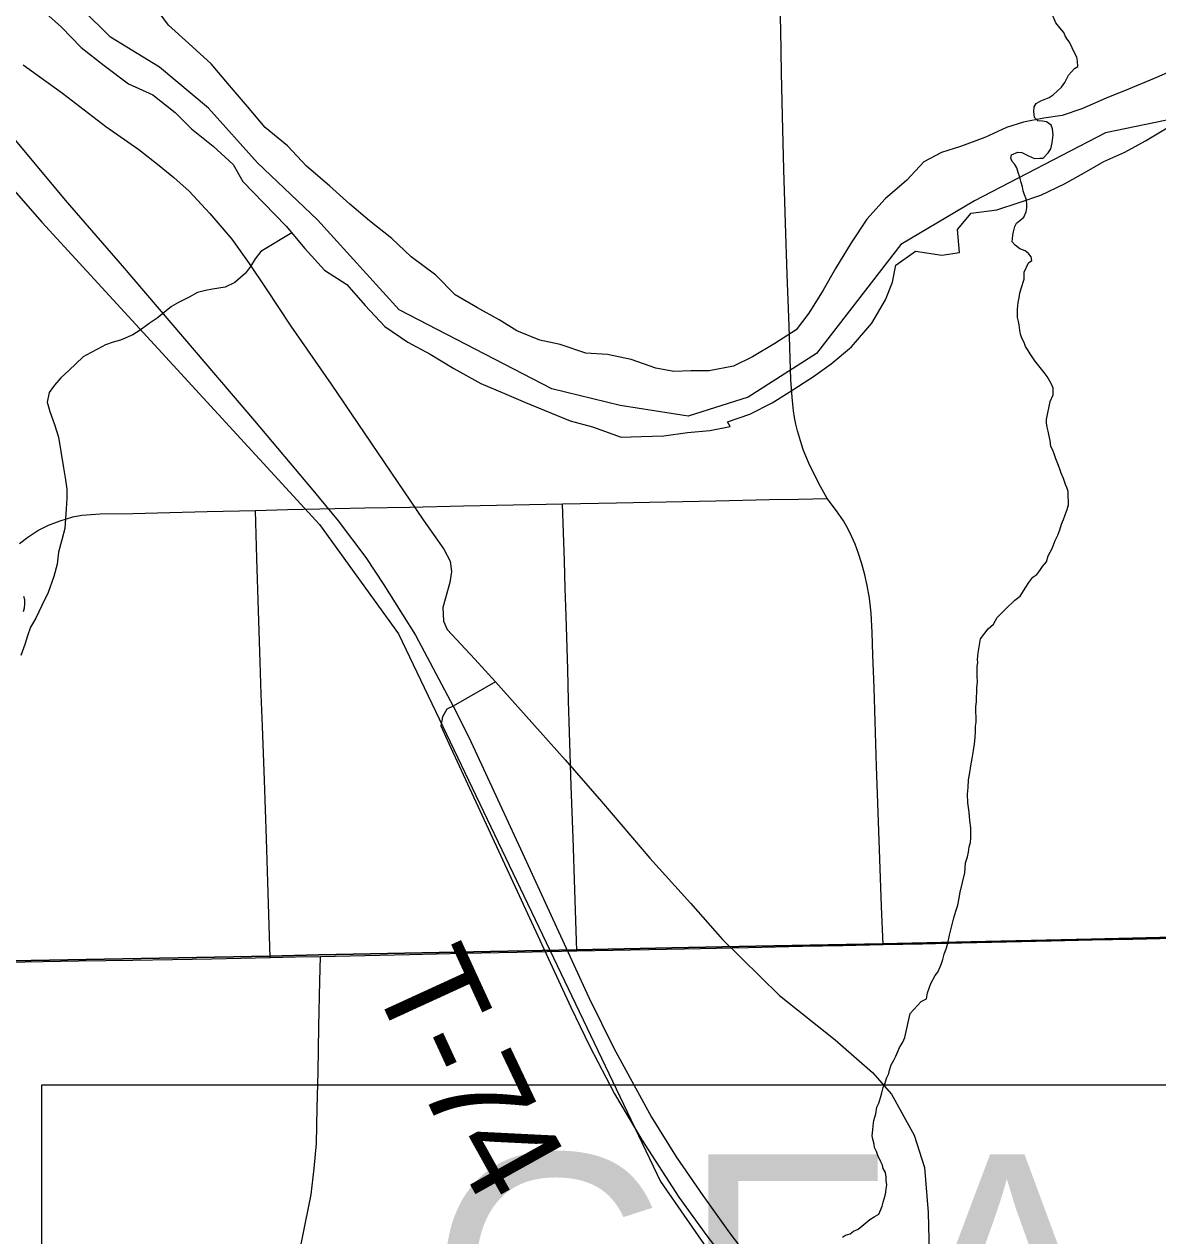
# Model space of a CAD drawing. Extents: x -6.1 to 38, y -7.7 to 22.
# Drawn here: x 3.606 to 4.259, y 19.227 to 19.926 of the extents above; entities that cross this region are included whole.
import ezdxf

# ---------------------------------------------------------------- set-up
doc = ezdxf.new("R2010")
doc.units = 0
for name, color, linetype in [('GM_X_Corporation', 7, 'Continuous'), ('GM_X_County_Road', 7, 'Continuous'), ('GM_X_Major_River', 7, 'Continuous'), ('GM_X_Minor_River', 7, 'Continuous'), ('GM_X_Rail_Line', 7, 'Continuous'), ('GM_X_Township_Road', 7, 'Continuous'), ('GM_X_Township_Road_Text', 7, 'Continuous'), ('GM_X_US_Route', 7, 'Continuous'), ('SH_Text', 7, 'Continuous')]:
    doc.layers.add(name, color=color, linetype=linetype)

msp = doc.modelspace()

# ---------------------------------------------------------------- linework, layer by layer
at = {"layer": 'GM_X_Corporation'}
for points in [[(6.96628, 20.9), (2.1, 20.9), (2.1, 19.36551), (3.07052, 19.37611), (3.09907, 19.37662), (3.10966, 19.37681), (3.12026, 19.377), (3.14426, 19.37751), (3.74766, 19.38857), (3.77587, 19.3894), (3.92442, 19.39221), (3.97926, 19.39329), (4.02764, 19.39424), (4.10065, 19.39567), (4.15155, 19.39684), (4.22089, 19.39843), (4.27649, 19.3997)], [(4.32021, 19.88191), (4.2291, 19.86308), (4.15368, 19.82382), (4.11127, 19.79868), (4.06254, 19.73585), (4.02327, 19.71072), (3.98871, 19.69973), (3.94944, 19.70602), (3.91017, 19.71546), (3.82222, 19.76103), (3.77511, 19.81289), (3.74056, 19.84589), (3.7123, 19.87731), (3.68403, 19.90089), (3.65576, 19.91817), (3.62279, 19.95117), (3.59767, 19.97946), (3.59394, 19.99773), (3.57833, 20.03194), (3.57893, 20.04876), (3.51164, 20.05197), (3.36656, 20.05475), (3.29133, 20.05869), (2.61918, 20.0796)], [(4.32021, 19.88191), (4.2291, 19.86308), (4.15368, 19.82382), (4.11127, 19.79868), (4.06254, 19.73585), (4.02327, 19.71072), (3.98871, 19.69973), (3.94944, 19.70602), (3.91017, 19.71546), (3.82222, 19.76103), (3.77511, 19.81289), (3.74056, 19.84589), (3.7123, 19.87731), (3.68403, 19.90089), (3.65576, 19.91817), (3.62279, 19.95117), (3.59767, 19.97946), (3.59394, 19.99773), (3.57833, 20.03194), (3.57893, 20.04876), (4.40517, 20.00794)], [(4.27649, 19.3997), (4.22089, 19.39843), (4.15155, 19.39684), (4.10065, 19.39567), (4.02764, 19.39424), (3.97926, 19.39329), (3.92442, 19.39221), (3.77587, 19.3894), (3.74766, 19.38857), (3.14426, 19.37751), (3.12026, 19.377), (3.10966, 19.37681), (3.09907, 19.37662), (3.07052, 19.37611), (2.1, 19.36551), (2.1, 14.52316)]]:
    msp.add_lwpolyline(points, dxfattribs=at)
at = {"layer": 'GM_X_County_Road'}
for points in [[(3.6054, 19.90225), (3.62817, 19.88592), (3.65318, 19.86676), (3.67211, 19.85357), (3.68391, 19.84417), (3.69222, 19.83739), (3.70118, 19.82952), (3.71298, 19.81663), (3.72568, 19.80178), (3.73571, 19.78778), (3.74554, 19.77313), (3.75976, 19.75171), (3.78292, 19.71827), (3.81374, 19.67281), (3.83603, 19.64003), (3.84783, 19.62319), (3.85155, 19.6162), (3.85221, 19.6103), (3.85133, 19.60396), (3.8474, 19.58953), (3.84762, 19.58167), (3.8498, 19.57686), (3.86576, 19.55981), (3.87762, 19.54657)], [(3.87762, 19.54657), (3.90335, 19.51785), (3.91778, 19.50167), (3.93868, 19.47776), (3.96652, 19.44507), (3.99, 19.41917), (4.0084, 19.3981), (4.04134, 19.3658), (4.07339, 19.34024), (4.09489, 19.32157), (4.10585, 19.30899), (4.11883, 19.28544), (4.12492, 19.26678), (4.12694, 19.2408), (4.12804, 19.19415), (4.12826, 19.14759), (4.12782, 19.13251), (4.1256, 19.12156), (4.12214, 19.11282)], [(3.77678, 19.38844), (3.80244, 19.38899), (3.82809, 19.38954), (3.85916, 19.39018), (3.89022, 19.39083), (3.90737, 19.39118), (3.92452, 19.39154), (3.95558, 19.39218), (3.98664, 19.39283), (4.00508, 19.39322), (4.02353, 19.3936), (4.05459, 19.39424), (4.07778, 19.39472), (4.10097, 19.3952), (4.12364, 19.39567), (4.14631, 19.39614), (4.17207, 19.39674), (4.19783, 19.39733), (4.2214, 19.39787), (4.24498, 19.39841), (4.26863, 19.39893), (4.29229, 19.39946), (4.30984, 19.39985), (4.32738, 19.40023)], [(3.21579, 19.37825), (3.24685, 19.37889), (3.27791, 19.37953), (3.30898, 19.38017), (3.32459, 19.38049), (3.34021, 19.38081), (3.37127, 19.38127), (3.40233, 19.38175), (3.43339, 19.38221), (3.45537, 19.38254), (3.47734, 19.38288), (3.5084, 19.38345), (3.53946, 19.38401), (3.57052, 19.38459), (3.58854, 19.38491), (3.60656, 19.38524), (3.63763, 19.38576), (3.66869, 19.38628), (3.69144, 19.38665), (3.71418, 19.38703), (3.73095, 19.38742), (3.74773, 19.3878), (3.76238, 19.38813), (3.77678, 19.38844)], [(3.73819, 19.0866), (3.74435, 19.11705), (3.7505, 19.14751), (3.75665, 19.17796), (3.76153, 19.20215), (3.76642, 19.22633), (3.77144, 19.25109), (3.77324, 19.26613), (3.77444, 19.28061), (3.77491, 19.30118), (3.77538, 19.32176), (3.77594, 19.34797), (3.77651, 19.37418), (3.77678, 19.38844)]]:
    msp.add_lwpolyline(points, dxfattribs=at)
at = {"layer": 'GM_X_Major_River'}
for points in [[(4.20427, 19.87308), (4.19368, 19.87155), (4.18197, 19.86925), (4.17214, 19.8662), (4.15967, 19.86049), (4.14569, 19.85516), (4.13474, 19.85172), (4.12454, 19.8464), (4.11473, 19.83576), (4.10227, 19.82513), (4.09171, 19.81336), (4.08266, 19.79969), (4.07361, 19.78489), (4.06645, 19.77237), (4.05816, 19.75909), (4.05099, 19.7496), (4.03853, 19.74161), (4.02569, 19.734), (4.01474, 19.72868), (4.00075, 19.726), (3.99017, 19.72598), (3.98034, 19.72558), (3.97013, 19.72745), (3.95575, 19.73235), (3.94213, 19.73536), (3.92965, 19.7361), (3.9149, 19.741), (3.90317, 19.74363), (3.88993, 19.74891), (3.87971, 19.75533), (3.86722, 19.76213), (3.85435, 19.76969), (3.84336, 19.78104), (3.82898, 19.79163), (3.81799, 19.80222), (3.80512, 19.81243), (3.79376, 19.82189), (3.78202, 19.83248), (3.76876, 19.84383), (3.75778, 19.85556), (3.7449, 19.86614), (3.73467, 19.87826), (3.72444, 19.89037), (3.71383, 19.90286), (3.70095, 19.91459), (3.68921, 19.92518), (3.6805, 19.93691)], [(3.61661, 19.93376), (3.62759, 19.92392), (3.63895, 19.91219)], [(3.63895, 19.91219), (3.6522, 19.90199), (3.66621, 19.8914), (3.68022, 19.88498), (3.69309, 19.87477), (3.70256, 19.86531), (3.71505, 19.85547), (3.72642, 19.84488), (3.73211, 19.83504), (3.74423, 19.82255), (3.75711, 19.80931), (3.76772, 19.79644), (3.77908, 19.78395), (3.79196, 19.77564), (3.80256, 19.76353), (3.81393, 19.75142), (3.82718, 19.74235), (3.84005, 19.73555), (3.85368, 19.72723), (3.86919, 19.71854), (3.88282, 19.71288), (3.89492, 19.7076), (3.92065, 19.69704), (3.93351, 19.69365), (3.95016, 19.68762), (3.9615, 19.68802), (3.97474, 19.68842), (3.98834, 19.69034), (4.0012, 19.6915), (4.01291, 19.6938)], [(4.26774, 19.89898), (4.25716, 19.89441), (4.24242, 19.88832), (4.22958, 19.88299), (4.2156, 19.8769), (4.20427, 19.87308)], [(4.01291, 19.6938), (4.01139, 19.69645), (4.02424, 19.70102), (4.03708, 19.70749), (4.0469, 19.71357), (4.06088, 19.7227), (4.07107, 19.72992), (4.08277, 19.7398), (4.09447, 19.75347), (4.10238, 19.76675), (4.10652, 19.77699), (4.10839, 19.78685), (4.11972, 19.79483), (4.13485, 19.79259), (4.14505, 19.79412), (4.14389, 19.80739), (4.15182, 19.81688), (4.16656, 19.8188), (4.1794, 19.823), (4.19187, 19.82719), (4.20547, 19.83366), (4.21831, 19.84089), (4.22813, 19.84659), (4.24022, 19.85192), (4.25231, 19.85839), (4.26477, 19.866)]]:
    msp.add_lwpolyline(points, dxfattribs=at)
at = {"layer": 'GM_X_Minor_River'}
for points in [[(4.20288, 19.92355), (4.20055, 19.92655), (4.19841, 19.93144)], [(4.19728, 19.6858), (4.19645, 19.68921), (4.19604, 19.6911), (4.19562, 19.69337), (4.19519, 19.69603), (4.19516, 19.69793), (4.19725, 19.70823), (4.19908, 19.71207), (4.19901, 19.71587), (4.19822, 19.71776), (4.19704, 19.72002), (4.19547, 19.72265), (4.19391, 19.7249), (4.19158, 19.7279), (4.19003, 19.72978), (4.18848, 19.73165), (4.18692, 19.7339), (4.18574, 19.73578), (4.18457, 19.73766), (4.18301, 19.73992), (4.18221, 19.74219), (4.18102, 19.74482), (4.18022, 19.74709), (4.1798, 19.74937), (4.17937, 19.7524), (4.17895, 19.75429), (4.17853, 19.75657), (4.17849, 19.75885), (4.17844, 19.76151), (4.17875, 19.76532), (4.17947, 19.76799), (4.1798, 19.77066), (4.18051, 19.77333), (4.18231, 19.77869), (4.18224, 19.78287), (4.1848, 19.78824), (4.18668, 19.78942), (4.18626, 19.79169), (4.18471, 19.79356), (4.18278, 19.79505), (4.17972, 19.79614), (4.17702, 19.79837), (4.17547, 19.80024), (4.17578, 19.80405), (4.17613, 19.80596), (4.17683, 19.80901), (4.17794, 19.81093), (4.17981, 19.81249), (4.18205, 19.81443), (4.18352, 19.8175), (4.18386, 19.81979), (4.18381, 19.82245), (4.18338, 19.8251), (4.18258, 19.82737), (4.18178, 19.82963), (4.18136, 19.83191), (4.18055, 19.83455), (4.17974, 19.83758), (4.17893, 19.84023), (4.17812, 19.84288), (4.17695, 19.84476), (4.1754, 19.84663), (4.1746, 19.84852), (4.17495, 19.85043), (4.17872, 19.85201), (4.181, 19.85168), (4.18483, 19.84984), (4.18828, 19.84838), (4.19132, 19.84844), (4.19322, 19.84847), (4.1962, 19.85157), (4.19768, 19.85387), (4.19837, 19.85731), (4.19905, 19.86189), (4.19861, 19.8653), (4.19781, 19.86757), (4.19512, 19.86942), (4.19283, 19.86976), (4.19017, 19.87009), (4.18824, 19.87196), (4.18779, 19.87537), (4.18813, 19.87804), (4.18923, 19.87996), (4.19186, 19.88153), (4.19375, 19.88232), (4.19676, 19.88352), (4.19901, 19.88508), (4.20126, 19.88702), (4.20388, 19.88935), (4.20572, 19.89204), (4.20793, 19.89627), (4.21128, 19.90013), (4.21315, 19.9013), (4.2131, 19.90435), (4.21268, 19.90662), (4.2115, 19.90888), (4.20835, 19.91529), (4.20717, 19.91717), (4.206, 19.91905), (4.20521, 19.92093), (4.20288, 19.92355)], [(3.76031, 19.80542), (3.74252, 19.79471), (3.73914, 19.79053), (3.73651, 19.78597), (3.73351, 19.78217), (3.72749, 19.77684), (3.72183, 19.77416), (3.71466, 19.77299), (3.71051, 19.77222), (3.70598, 19.77106), (3.70108, 19.76839), (3.69505, 19.76533), (3.6909, 19.76304), (3.68262, 19.75618), (3.67811, 19.75313), (3.67283, 19.74932), (3.66869, 19.74665), (3.66153, 19.74358), (3.65738, 19.74243), (3.65285, 19.74089), (3.6487, 19.7386), (3.64418, 19.73631), (3.64003, 19.73402), (3.63176, 19.72603), (3.62724, 19.72184), (3.62349, 19.71765), (3.62048, 19.71347), (3.61938, 19.70778), (3.62091, 19.70248), (3.62359, 19.69491), (3.62589, 19.68772), (3.62745, 19.67824), (3.62862, 19.66991), (3.62979, 19.66309), (3.63057, 19.65779), (3.63059, 19.65248), (3.63024, 19.64642), (3.62954, 19.63504), (3.62768, 19.62859), (3.62582, 19.62138), (3.6251, 19.61456), (3.62324, 19.60735), (3.61989, 19.59824), (3.61614, 19.59064), (3.61278, 19.58342), (3.60978, 19.57811), (3.60791, 19.57317), (3.60643, 19.56824), (3.60419, 19.56178)], [(4.11235, 19.33899), (4.11344, 19.34167), (4.11661, 19.35541), (4.12295, 19.36237), (4.12596, 19.36395), (4.12665, 19.36738), (4.12846, 19.37274), (4.13103, 19.37735), (4.13252, 19.37928), (4.13398, 19.38235), (4.13471, 19.38426), (4.13542, 19.38656), (4.13613, 19.38961), (4.13758, 19.39344), (4.13829, 19.39611), (4.13935, 19.4007), (4.14005, 19.40375), (4.14076, 19.40681), (4.14183, 19.41063), (4.1429, 19.41445), (4.14398, 19.41789), (4.14468, 19.42095), (4.14536, 19.42552), (4.1482, 19.4366), (4.14848, 19.44231), (4.14955, 19.44575), (4.15026, 19.44843), (4.15059, 19.45148), (4.1513, 19.45415), (4.15163, 19.45682), (4.15158, 19.45948), (4.15153, 19.46252), (4.15108, 19.46669), (4.15061, 19.47163), (4.15018, 19.47428), (4.14975, 19.47694), (4.14966, 19.48188), (4.14997, 19.48569), (4.15027, 19.49026), (4.15096, 19.49445), (4.15165, 19.49827), (4.15233, 19.50246), (4.15301, 19.50704), (4.1537, 19.51085), (4.15401, 19.51466), (4.15433, 19.51809), (4.15428, 19.52113), (4.15461, 19.52342), (4.15457, 19.52608), (4.15451, 19.5295), (4.15445, 19.53254), (4.15478, 19.53521), (4.15474, 19.53787), (4.15507, 19.54054), (4.15502, 19.5432), (4.15534, 19.54663), (4.15528, 19.54967), (4.15524, 19.55233), (4.15517, 19.55575), (4.15552, 19.55766), (4.15549, 19.55956), (4.1558, 19.56337), (4.15717, 19.57138), (4.16162, 19.57716), (4.16461, 19.57988), (4.16682, 19.58372), (4.17167, 19.58875), (4.1769, 19.59379), (4.1799, 19.59612), (4.18322, 19.60113), (4.18507, 19.60382), (4.1873, 19.6069), (4.18955, 19.60847), (4.1914, 19.61078), (4.19289, 19.61309), (4.19511, 19.61579), (4.19619, 19.61923), (4.1984, 19.62346), (4.20021, 19.62805), (4.20168, 19.63112), (4.20276, 19.63418), (4.20384, 19.63762), (4.20493, 19.6403), (4.20602, 19.64299), (4.20711, 19.64605), (4.20782, 19.64872), (4.20778, 19.651), (4.20773, 19.65328), (4.20768, 19.65633), (4.20688, 19.65859), (4.20608, 19.66048), (4.20489, 19.66388), (4.20369, 19.6669), (4.20289, 19.66917), (4.20209, 19.67143), (4.2013, 19.67332), (4.2005, 19.67521), (4.1997, 19.67747), (4.1989, 19.68012), (4.19772, 19.68238), (4.19728, 19.6858)], [(4.07753, 19.22656), (4.07941, 19.22773), (4.08205, 19.22854), (4.08392, 19.23009), (4.08656, 19.23128), (4.08881, 19.23284), (4.09106, 19.23478), (4.0933, 19.23672), (4.09593, 19.23829), (4.09856, 19.23986), (4.09965, 19.24254), (4.10038, 19.24446), (4.10109, 19.24675), (4.10216, 19.25058), (4.10251, 19.25248), (4.10286, 19.25439), (4.10319, 19.25668), (4.10277, 19.25933), (4.10273, 19.26123), (4.10231, 19.26389), (4.10113, 19.26615), (4.10071, 19.26804), (4.09953, 19.2703), (4.09795, 19.2737), (4.09715, 19.27597), (4.09597, 19.27822), (4.09594, 19.28013), (4.09512, 19.28315), (4.09471, 19.28505), (4.09503, 19.28848), (4.09537, 19.29076), (4.09569, 19.29381), (4.09676, 19.29764), (4.09745, 19.30145), (4.09855, 19.30375), (4.09962, 19.30757), (4.10034, 19.30987), (4.10104, 19.31292), (4.10214, 19.31561), (4.10322, 19.31867), (4.10432, 19.32097), (4.10466, 19.32288), (4.10575, 19.32594), (4.10722, 19.32863), (4.10832, 19.33093), (4.10941, 19.33361), (4.11051, 19.33591), (4.11235, 19.33899)]]:
    msp.add_lwpolyline(points, dxfattribs=at)
at = {"layer": 'GM_X_Rail_Line'}
msp.add_lwpolyline([(2.1, 20.22672), (2.72238, 19.85623), (2.78818, 19.82405), (2.83715, 19.81025), (2.88459, 19.81024), (2.93803, 19.82546), (2.99132, 19.87524), (3.04538, 19.90505), (3.0964, 19.92627), (3.15298, 19.92829), (3.20022, 19.92551), (3.24316, 19.93561), (3.30555, 19.95557), (3.37905, 19.97249), (3.43412, 19.97653), (3.46898, 19.97552), (3.495, 19.95808), (3.54553, 19.89238), (3.61618, 19.81161), (3.7762, 19.63742), (3.82168, 19.57425), (3.97265, 19.2587), (4.0109, 19.20357)], dxfattribs=at)
at = {"layer": 'GM_X_Township_Road'}
msp.add_line((3.87762, 19.54657), (3.85332, 19.53273), dxfattribs=at)
for points in [[(4.10097, 19.3952), (4.10014, 19.41711), (4.09912, 19.44436), (4.09809, 19.47161), (4.09728, 19.49782), (4.09646, 19.52402), (4.0958, 19.54313), (4.09513, 19.56224), (4.09476, 19.57507), (4.09415, 19.58629), (4.09316, 19.59492), (4.09188, 19.60213), (4.09055, 19.60832), (4.08872, 19.61473), (4.08687, 19.62056), (4.08496, 19.62602), (4.08305, 19.63031), (4.08096, 19.63463), (4.07812, 19.63939), (4.07421, 19.6452), (4.06887, 19.65238), (4.06492, 19.65928), (4.05993, 19.66911), (4.05822, 19.67267), (4.05666, 19.67628), (4.05519, 19.67995), (4.05392, 19.68368), (4.05274, 19.68744), (4.05169, 19.69124), (4.0508, 19.69508), (4.05004, 19.69895), (4.04943, 19.70284), (4.04895, 19.70677), (4.04862, 19.71069), (4.0479, 19.72081), (4.0468, 19.75186), (4.04575, 19.7814), (4.0447, 19.81094), (4.04383, 19.84189), (4.04297, 19.87284), (4.04248, 19.89769), (4.04199, 19.92253), (4.04156, 19.94312)], [(3.60332, 19.6263), (3.60813, 19.63), (3.61396, 19.63389), (3.62006, 19.63694), (3.62681, 19.63953), (3.63411, 19.64175), (3.6393, 19.64267), (3.64457, 19.64313), (3.64993, 19.6434), (3.66861, 19.64378), (3.69006, 19.64434), (3.71152, 19.64489), (3.73936, 19.64545), (3.75785, 19.64596), (3.77635, 19.64646), (3.80228, 19.64692), (3.82822, 19.64738), (3.85929, 19.64802), (3.8878, 19.64861), (3.9163, 19.6492), (3.94737, 19.64984), (3.97595, 19.65043), (4.00453, 19.65102), (4.03559, 19.65167), (4.05223, 19.65202), (4.06887, 19.65238)], [(3.74773, 19.3878), (3.74715, 19.40646), (3.74658, 19.42511), (3.74563, 19.45617), (3.74511, 19.47311), (3.74459, 19.49006), (3.74338, 19.52111), (3.74266, 19.53954), (3.74195, 19.55796), (3.74106, 19.58783), (3.74019, 19.6177), (3.73936, 19.64545)], [(3.92452, 19.39154), (3.92396, 19.40915), (3.92339, 19.42675), (3.92236, 19.45668), (3.92132, 19.48661), (3.92037, 19.51767), (3.91981, 19.53568), (3.91925, 19.55368), (3.91829, 19.58473), (3.9178, 19.60053), (3.91732, 19.61633), (3.91681, 19.63277), (3.9163, 19.6492)], [(3.60557, 19.58721), (3.60624, 19.58935), (3.60651, 19.59171), (3.60644, 19.59386), (3.60589, 19.59593)], [(3.85332, 19.53273), (3.84967, 19.5309), (3.84707, 19.52657), (3.84609, 19.52135), (3.85068, 19.51107), (3.92106, 19.35917), (3.93176, 19.33687), (3.94619, 19.30912), (3.96193, 19.28267), (3.98335, 19.24966), (3.99952, 19.22737), (4.01116, 19.21217)]]:
    msp.add_lwpolyline(points, dxfattribs=at)
at = {"layer": 'GM_X_US_Route'}
for points in [[(3.52742, 19.94405), (3.54971, 19.91826), (3.59233, 19.86908), (3.62971, 19.82428), (3.66249, 19.78647), (3.73877, 19.69707), (3.77236, 19.65718), (3.78708, 19.63937), (3.80303, 19.61839), (3.81329, 19.60263), (3.82397, 19.58555), (3.83159, 19.57365), (3.85332, 19.53273), (3.86226, 19.51478), (3.87072, 19.49655)], [(3.87072, 19.49655), (3.89439, 19.4455), (3.93153, 19.36473), (3.94576, 19.33556), (3.96761, 19.29578), (3.98182, 19.27284), (3.99711, 19.25054), (4.01242, 19.22912), (4.02728, 19.20967), (4.05023, 19.183), (4.07143, 19.16049), (4.08969, 19.14182), (4.12214, 19.11282), (4.13984, 19.09776), (4.17067, 19.07419), (4.31338, 18.9664), (4.396, 18.90477), (4.50762, 18.82015), (4.55379, 18.78471), (4.58065, 18.76511)]]:
    msp.add_lwpolyline(points, dxfattribs=at)
at = {"layer": 'SH_Text'}
msp.add_lwpolyline([(3.61627, 19.3143), (5.44915, 19.3143), (5.44915, 18.64981), (3.61627, 18.64981)], close=True, dxfattribs=at)

# ---------------------------------------------------------------- texts
at = {"layer": 'GM_X_Township_Road_Text'}
for s, rotation, p in [('T', 294.63656, (3.80546, 19.37569)), ('-', 294.7531, (3.82323, 19.33695)), ('7', 295.39727, (3.83329, 19.31512)), ('4', 299.12965, (3.85016, 19.27992))]:
    msp.add_text(s, height=0.05682, rotation=rotation, dxfattribs=at).set_placement(p)
at = {"layer": 'SH_Text'}
msp.add_text('GEA-44-14.93', height=0.1399997, dxfattribs=at).set_placement((3.83924, 19.1344))

doc.saveas('drawing.dxf')
